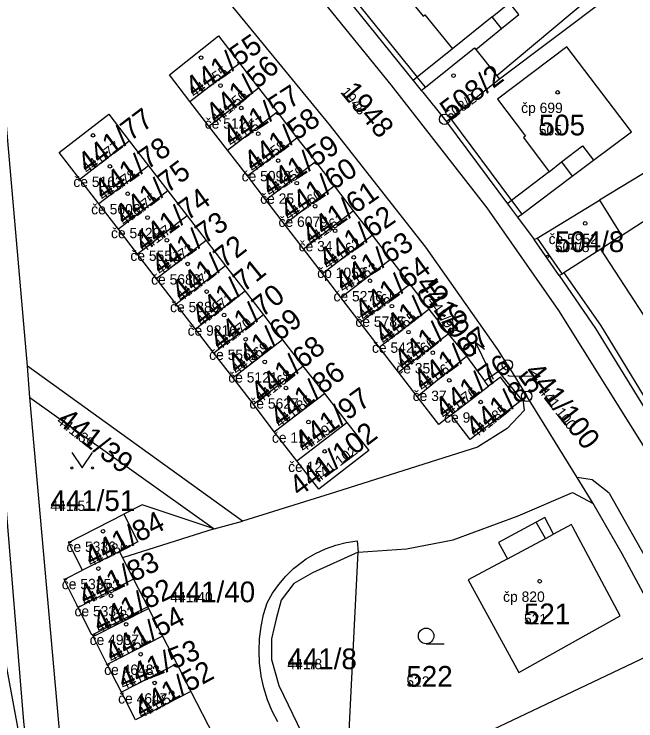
# Model space of a CAD drawing. Extents: x -763628 to -761565, y -976033 to -973833.
# Drawn here: x -762097.5 to -762037.5, y -974221.8 to -974153.6 of the extents above; entities that cross this region are included whole.
import ezdxf

# ---------------------------------------------------------------- set-up
doc = ezdxf.new("R2010")
doc.units = 0
for name, color, linetype in [('KN_cisla parcel 1000', 7, 'Continuous'), ('KN_cisla parcel 500', 7, 'Continuous'), ('KN_cisla parcel znacky', 7, 'Continuous'), ('KN_cisla popisna 500', 7, 'Continuous'), ('KN_hranice parcel', 7, 'Continuous'), ('KN_vnitrni kresba parcel', 7, 'Continuous'), ('KN_znacky bodu BP', 7, 'Continuous'), ('KN_znacky budov', 7, 'Continuous'), ('KN_znacky kultur', 7, 'Continuous')]:
    doc.layers.add(name, color=color, linetype=linetype)

msp = doc.modelspace()

# ---------------------------------------------------------------- linework, layer by layer
at = {"layer": 'KN_cisla parcel znacky'}
for p, q in [((-762052.966, -974185.263), (-762052.977, -974186.382)), ((-762051.65, -974187.96), (-762052.966, -974185.263)), ((-762052.966, -974185.263), (-762052.076, -974185.943)), ((-762051.21, -974188.86), (-762051.65, -974187.96)), ((-762049.72, -974188.5), (-762049.82, -974188.5)), ((-762049.72, -974188.5), (-762046.719, -974188.552)), ((-762046.719, -974188.552), (-762047.73, -974189.036)), ((-762046.719, -974188.552), (-762047.712, -974188.034))]:
    msp.add_line(p, q, dxfattribs=at)
at = {"layer": 'KN_hranice parcel'}
for p, q in [((-762009.82, -974125.16), (-762050.89, -974159.55)), ((-762007.44, -974127.35), (-762050.63, -974159.87)), ((-762065.64, -974151.72), (-762058.96, -974160)), ((-762013.14, -974154.55), (-762040.98, -974171.55)), ((-762052.93, -974157.02), (-762050.89, -974159.55)), ((-762080.5, -974162.03), (-762075.7, -974158.34)), ((-762075.7, -974158.34), (-762073.87, -974160.72)), ((-762058.96, -974160), (-762058.18, -974160.97)), ((-762050.89, -974159.55), (-762050.63, -974159.87)), ((-762078.66, -974164.41), (-762073.87, -974160.72)), ((-762073.87, -974160.72), (-762072.08, -974163.05)), ((-762078.66, -974164.41), (-762080.5, -974162.03)), ((-762076.87, -974166.74), (-762072.08, -974163.05)), ((-762072.08, -974163.05), (-762070.17, -974165.53)), ((-762055.74, -974163.99), (-762049.87, -974171.9)), ((-762076.87, -974166.74), (-762078.66, -974164.41)), ((-762091.12, -974169.52), (-762086.35, -974165.84)), ((-762086.35, -974165.84), (-762084.5, -974168.24)), ((-762074.96, -974169.22), (-762070.17, -974165.53)), ((-762070.17, -974165.53), (-762068.39, -974167.84)), ((-762074.96, -974169.22), (-762076.87, -974166.74)), ((-762073.19, -974171.53), (-762068.39, -974167.84)), ((-762068.39, -974167.84), (-762066.59, -974170.18)), ((-762084.5, -974168.24), (-762089.27, -974171.92)), ((-762084.5, -974168.24), (-762082.63, -974170.67)), ((-762089.27, -974171.92), (-762091.12, -974169.52)), ((-762073.19, -974171.53), (-762074.96, -974169.22)), ((-762071.38, -974173.87), (-762066.59, -974170.18)), ((-762066.59, -974170.18), (-762064.74, -974172.58)), ((-762082.63, -974170.67), (-762087.4, -974174.35)), ((-762082.63, -974170.67), (-762080.77, -974173.08)), ((-762071.38, -974173.87), (-762073.19, -974171.53)), ((-762040.98, -974171.55), (-762038.86, -974174.98)), ((-762087.4, -974174.35), (-762089.27, -974171.92)), ((-762049.87, -974171.9), (-762048.9, -974173.21)), ((-762069.53, -974176.27), (-762064.74, -974172.58)), ((-762064.74, -974172.58), (-762062.93, -974174.94)), ((-762080.77, -974173.08), (-762085.55, -974176.76)), ((-762080.77, -974173.08), (-762078.93, -974175.46)), ((-762048.9, -974173.21), (-762047.31, -974175.35)), ((-762085.55, -974176.76), (-762087.4, -974174.35)), ((-762069.53, -974176.27), (-762071.38, -974173.87)), ((-762067.72, -974178.63), (-762062.93, -974174.94)), ((-762062.93, -974174.94), (-762061.14, -974177.26)), ((-762038.86, -974174.98), (-762040.88, -974176.3)), ((-762078.93, -974175.46), (-762083.71, -974179.14)), ((-762078.93, -974175.46), (-762077.05, -974177.91)), ((-762044.9, -974178.83), (-762047.31, -974175.35)), ((-762067.72, -974178.63), (-762069.53, -974176.27)), ((-762083.71, -974179.14), (-762085.55, -974176.76)), ((-762065.93, -974180.95), (-762061.14, -974177.26)), ((-762061.14, -974177.26), (-762059.28, -974179.68)), ((-762077.05, -974177.91), (-762081.82, -974181.59)), ((-762077.05, -974177.91), (-762075.18, -974180.33)), ((-762065.93, -974180.95), (-762067.72, -974178.63)), ((-762081.82, -974181.59), (-762083.71, -974179.14)), ((-762064.07, -974183.37), (-762059.28, -974179.68)), ((-762059.28, -974179.68), (-762057.44, -974182.07)), ((-762075.18, -974180.33), (-762079.96, -974184.01)), ((-762075.18, -974180.33), (-762073.41, -974182.63)), ((-762064.07, -974183.37), (-762065.93, -974180.95)), ((-762079.96, -974184.01), (-762081.82, -974181.59)), ((-762062.23, -974185.76), (-762057.44, -974182.07)), ((-762057.44, -974182.07), (-762055.59, -974184.46)), ((-762073.41, -974182.63), (-762078.19, -974186.31)), ((-762073.41, -974182.63), (-762071.56, -974185.03)), ((-762062.23, -974185.76), (-762064.07, -974183.37)), ((-762078.19, -974186.31), (-762079.96, -974184.01)), ((-762060.39, -974188.15), (-762055.59, -974184.46)), ((-762055.59, -974184.46), (-762053.81, -974186.61)), ((-762071.56, -974185.03), (-762076.33, -974188.71)), ((-762071.56, -974185.03), (-762069.6, -974187.57)), ((-762060.39, -974188.15), (-762062.23, -974185.76)), ((-762076.33, -974188.71), (-762078.19, -974186.31)), ((-762058.57, -974190.52), (-762053.81, -974186.61)), ((-762053.81, -974186.61), (-762052.08, -974189)), ((-762095.95, -974190.59), (-762096.15, -974187.58)), ((-762075.42, -974202.52), (-762096.15, -974187.58)), ((-762074.37, -974191.25), (-762069.6, -974187.57)), ((-762069.6, -974187.57), (-762067.53, -974190.21)), ((-762050.72, -974188.05), (-762049.88, -974187.46)), ((-762058.57, -974190.52), (-762060.39, -974188.15)), ((-762052.08, -974189), (-762050.72, -974188.05)), ((-762048.48, -974190.83), (-762050.72, -974188.05)), ((-762074.37, -974191.25), (-762076.33, -974188.71)), ((-762051.7, -974189.52), (-762052.08, -974189)), ((-762055.3, -974192.29), (-762051.7, -974189.52)), ((-762092.91, -974224.57), (-762095.95, -974190.59)), ((-762095.95, -974190.59), (-762078.17, -974203.27)), ((-762072.36, -974193.92), (-762067.53, -974190.21)), ((-762067.53, -974190.21), (-762065.35, -974193.02)), ((-762048.01, -974190.48), (-762048.38, -974190.75)), ((-762072.36, -974193.92), (-762074.37, -974191.25)), ((-762048.48, -974190.83), (-762048.71, -974191.01)), ((-762048.38, -974190.75), (-762048.48, -974190.83)), ((-762070.19, -974196.72), (-762065.35, -974193.02)), ((-762070.19, -974196.72), (-762072.36, -974193.92)), ((-762078.17, -974203.27), (-762075.42, -974202.52)), ((-762064.38, -974204.42), (-762064.27, -974205.53)), ((-762087.3, -974205.45), (-762090.86, -974207.26)), ((-762065.49, -974229.39), (-762064.27, -974205.53)), ((-762085.93, -974208.12), (-762091.28, -974210.85)), ((-762085.93, -974208.12), (-762084.57, -974210.79)), ((-762084.57, -974210.79), (-762084.49, -974210.95)), ((-762084.49, -974210.95), (-762083.13, -974213.62)), ((-762083.13, -974213.62), (-762088.47, -974216.35)), ((-762083.13, -974213.62), (-762081.76, -974216.29)), ((-762087.11, -974219.02), (-762088.47, -974216.35)), ((-762081.76, -974216.29), (-762087.11, -974219.02)), ((-762081.76, -974216.29), (-762080.4, -974218.97)), ((-762080.4, -974218.97), (-762078.2, -974223.27))]:
    msp.add_line(p, q, dxfattribs=at)
for points in [[(-762095.33, -974232.49), (-762096.53, -974221.88), (-762099.3, -974188.16), (-762099.59, -974185.1), (-762102.09, -974155.55), (-762101.7, -974155.58), (-762101.97, -974152.44), (-762102.63, -974146.99), (-762101.97, -974146.87), (-762103.48, -974129.95), (-762106.04, -974105.14), (-762113.51, -974051.11), (-762116.06, -974049.38)], [(-762095.33, -974232.49), (-762097.17, -974222.06), (-762100.03, -974206.75), (-762102.48, -974185.96), (-762102.8, -974182.73), (-762109.69, -974112.17), (-762112.36, -974090.26), (-762116.1, -974069.05), (-762118.4, -974057.49)], [(-762096.15, -974187.58), (-762099, -974155.5), (-762099.6, -974155.46), (-762099.73, -974152.5), (-762097.25, -974152.2), (-762097.79, -974146.39), (-762099.76, -974146.71), (-762101.36, -974130.74), (-762099.97, -974129.78), (-762093.64, -974131.74)], [(-762049.88, -974187.46), (-762050.81, -974185.98), (-762057.75, -974176.1), (-762067.06, -974164.24), (-762088, -974138.7)], [(-762052.93, -974157.02), (-762050.43, -974155), (-762048.77, -974153.66), (-762049.69, -974152.52), (-762048.75, -974151.76), (-762054.26, -974144.85), (-762060.82, -974150.05), (-762060.72, -974150.18), (-762060.87, -974150.3), (-762058, -974153.81), (-762057.85, -974153.69), (-762055.18, -974156.95), (-762058.57, -974159.68), (-762058.96, -974160)], [(-762080.5, -974162.03), (-762082.46, -974159.47), (-762077.73, -974155.71), (-762075.7, -974158.34)], [(-762058.18, -974160.97), (-762057.79, -974160.66), (-762053.06, -974156.85), (-762052.93, -974157.02)], [(-762048.9, -974173.21), (-762048.5, -974172.91), (-762043.62, -974169.24), (-762041.58, -974167.71), (-762037.92, -974164.96), (-762044.15, -974156.75), (-762050.83, -974161.82), (-762048.13, -974165.37), (-762048.33, -974165.52), (-762045.86, -974168.84), (-762049.47, -974171.6), (-762049.87, -974171.9)], [(-762050.63, -974159.87), (-762055.36, -974163.68), (-762055.74, -974163.99)], [(-762058.18, -974160.97), (-762058.03, -974161.14), (-762055.93, -974163.76), (-762055.74, -974163.99)], [(-762091.12, -974169.52), (-762093.1, -974166.96), (-762088.33, -974163.27), (-762086.35, -974165.84)], [(-762038.86, -974174.98), (-762035.43, -974172.74), (-762035.05, -974173.33), (-762029.61, -974169.78), (-762024.89, -974176.89), (-762029.9, -974180.17), (-762027.95, -974183.11), (-762033.96, -974186.9), (-762040.88, -974176.3)], [(-762047.31, -974175.35), (-762047.01, -974175.22), (-762046.85, -974175.13), (-762040.98, -974171.55)], [(-762040.88, -974176.3), (-762044.43, -974178.58), (-762044.61, -974178.69), (-762044.9, -974178.83)], [(-762044.9, -974178.83), (-762041.37, -974183.93), (-762036.34, -974192.15)], [(-762049.88, -974187.46), (-762048.48, -974189.71), (-762048.01, -974190.48)], [(-762048.71, -974191.01), (-762050.55, -974188.63), (-762051.7, -974189.52)], [(-762055.3, -974192.29), (-762056.5, -974193.21), (-762058.57, -974190.52)], [(-762041.61, -974200.83), (-762043.16, -974198.32), (-762048.01, -974190.48)], [(-762048.38, -974190.75), (-762048.27, -974191.86), (-762049.89, -974193.6), (-762052.75, -974195.4), (-762066.45, -974199.74), (-762075.42, -974202.52)], [(-762048.71, -974191.01), (-762053.47, -974194.67), (-762055.3, -974192.29)], [(-762065.35, -974193.02), (-762063.25, -974195.73), (-762068.07, -974199.46), (-762070.19, -974196.72)], [(-762064.27, -974205.53), (-762059.62, -974205.2), (-762055.12, -974204.33), (-762048.84, -974202.02), (-762043.61, -974199.77), (-762041.61, -974200.83)], [(-762034.09, -974214.47), (-762038.82, -974205.69), (-762041.61, -974200.83)], [(-762078.17, -974203.27), (-762085.1, -974200.96), (-762086.88, -974201.87)], [(-762090.86, -974207.26), (-762092.22, -974204.59), (-762086.88, -974201.87)], [(-762086.88, -974201.87), (-762085.52, -974204.54), (-762087.3, -974205.45)], [(-762053.66, -974208.21), (-762048.76, -974217.13), (-762039, -974211.66), (-762043.57, -974203.12), (-762043.71, -974202.86), (-762045.42, -974203.78), (-762046.28, -974202.17), (-762047.09, -974202.62), (-762050.73, -974204.59), (-762049.87, -974206.17), (-762053.66, -974208.21)], [(-762072.02, -974221.91), (-762072.558, -974220.856), (-762073.005, -974219.761), (-762073.358, -974218.631), (-762073.615, -974217.476), (-762073.626, -974217.412), (-762073.779, -974216.238), (-762073.832, -974215.056), (-762073.785, -974213.874), (-762073.638, -974212.7), (-762073.392, -974211.543), (-762073.05, -974210.41), (-762072.532, -974209.496), (-762071.929, -974208.636), (-762071.248, -974207.837), (-762070.493, -974207.107), (-762070.126, -974206.798), (-762069.278, -974206.178), (-762068.374, -974205.643), (-762067.424, -974205.195), (-762066.436, -974204.84), (-762065.418, -974204.581), (-762064.38, -974204.42)], [(-762087.3, -974205.45), (-762086.99, -974206.06), (-762085.93, -974208.12)], [(-762064.27, -974205.53), (-762068.69, -974207.52), (-762070.47, -974208.56), (-762071.7, -974210.16), (-762072.19, -974211.96), (-762072.64, -974213.9), (-762072.64, -974215.87), (-762071.92, -974218.39), (-762066.57, -974229.46)], [(-762091.28, -974210.85), (-762092.64, -974208.17), (-762090.86, -974207.26)], [(-762084.57, -974210.79), (-762089.97, -974213.55), (-762091.28, -974210.85)], [(-762088.47, -974216.35), (-762089.84, -974213.68), (-762084.49, -974210.95)], [(-762065.49, -974229.39), (-762034.5, -974214.66), (-762034.09, -974214.47)], [(-762080.4, -974218.97), (-762085.74, -974221.7), (-762087.11, -974219.02)]]:
    msp.add_lwpolyline(points, dxfattribs=at)
at = {"layer": 'KN_vnitrni kresba parcel'}
for p, q in [((-762080.56, -974136.43), (-762061.12, -974160.42)), ((-762065.25, -974151.4), (-762058.57, -974159.68)), ((-762051.35, -974153.86), (-762049.69, -974152.52)), ((-762051.35, -974153.86), (-762055.18, -974156.95)), ((-762050.43, -974155), (-762051.35, -974153.86)), ((-762057.79, -974160.66), (-762058.57, -974159.68)), ((-762061.12, -974160.42), (-762051.86, -974172.31)), ((-762055.36, -974163.68), (-762049.47, -974171.6)), ((-762044.67, -974167.85), (-762042.63, -974166.32)), ((-762042.63, -974166.32), (-762041.58, -974167.71)), ((-762045.86, -974168.84), (-762044.67, -974167.85)), ((-762044.67, -974167.85), (-762043.62, -974169.24)), ((-762049.47, -974171.6), (-762048.5, -974172.91)), ((-762051.86, -974172.31), (-762044.94, -974182.2)), ((-762047.01, -974175.22), (-762044.61, -974178.69)), ((-762044.43, -974178.58), (-762040.9, -974183.62)), ((-762044.94, -974182.2), (-762035.7, -974197.02)), ((-762040.9, -974183.62), (-762035.87, -974191.86)), ((-762041.7, -974198.56), (-762043.16, -974198.32)), ((-762040.07, -974199.84), (-762041.7, -974198.56)), ((-762040.07, -974199.84), (-762032.28, -974213.63)), ((-762046.21, -974204.2), (-762047.09, -974202.62)), ((-762078.17, -974203.27), (-762086.99, -974206.06)), ((-762049.87, -974206.17), (-762046.21, -974204.2)), ((-762046.21, -974204.2), (-762045.42, -974203.78))]:
    msp.add_line(p, q, dxfattribs=at)
at = {"layer": 'KN_znacky bodu BP'}
for centre, radius in [((-762055.93, -974163.76), 0.5), ((-762055.93, -974163.76), 0.0303), ((-762049.88, -974187.46), 0.5), ((-762049.88, -974187.46), 0.0303), ((-762048.01, -974190.48), 0.5), ((-762048.01, -974190.48), 0.0303)]:
    msp.add_circle(centre, radius, dxfattribs=at)
at = {"layer": 'KN_znacky budov'}
for centre, radius in [((-762079.417, -974157.809), 0.175), ((-762055.077, -974159.539), 0.175), ((-762077.547, -974160.499), 0.175), ((-762045.027, -974161.159), 0.175), ((-762075.547, -974162.669), 0.175), ((-762089.847, -974165.309), 0.175), ((-762073.907, -974165.149), 0.175), ((-762088.217, -974168.299), 0.175), ((-762071.987, -974167.749), 0.175), ((-762070.197, -974169.919), 0.175), ((-762086.497, -974170.939), 0.175), ((-762068.427, -974172.149), 0.175), ((-762084.587, -974173.239), 0.175), ((-762042.377, -974173.809), 0.175), ((-762066.487, -974174.509), 0.175), ((-762082.717, -974175.429), 0.175), ((-762064.697, -974177.079), 0.175), ((-762045.992, -974176.986), 0.117), ((-762080.717, -974177.719), 0.175), ((-762063.127, -974179.339), 0.175), ((-762078.887, -974180.379), 0.175), ((-762061.017, -974181.789), 0.175), ((-762077.197, -974182.649), 0.175), ((-762059.417, -974184.299), 0.175), ((-762075.117, -974184.979), 0.175), ((-762057.067, -974186.289), 0.175), ((-762073.277, -974187.169), 0.175), ((-762055.487, -974188.949), 0.175), ((-762071.237, -974189.689), 0.175), ((-762052.457, -974191.039), 0.175), ((-762069.067, -974192.979), 0.175), ((-762067.497, -974195.799), 0.175), ((-762088.877, -974203.509), 0.175), ((-762089.327, -974207.109), 0.175), ((-762046.767, -974208.329), 0.175), ((-762088.107, -974209.729), 0.175), ((-762086.647, -974212.489), 0.175), ((-762085.247, -974215.379), 0.175), ((-762083.897, -974218.149), 0.175)]:
    msp.add_circle(centre, radius, dxfattribs=at)
at = {"layer": 'KN_znacky kultur'}
msp.add_line((-762057.713, -974214.36), (-762055.963, -974214.36), dxfattribs=at)
msp.add_lwpolyline([(-762091.89, -974195.899), (-762090.89, -974197.4), (-762089.89, -974195.899)], dxfattribs=at)
for centre, radius in [((-762091.89, -974197.399), 0.1), ((-762089.89, -974197.399), 0.1), ((-762057.713, -974213.61), 0.75)]:
    msp.add_circle(centre, radius, dxfattribs=at)

# ---------------------------------------------------------------- texts
at = {"layer": 'KN_cisla parcel 1000'}
for s, rotation, p in [('441/55', 35, (-762080.075, -974161.711)), ('441/56', 41, (-762077.916, -974164.292)), ('508/2', 37, (-762055.418, -974163.968)), ('441/57', 33, (-762076.513, -974166.443)), ('1948', 310, (-762066.031, -974161.166)), ('441/77', 37, (-762090.388, -974169.059)), ('441/58', 36, (-762074.397, -974168.915)), ('441/59', 33, (-762072.773, -974171.243)), ('441/78', 35, (-762088.875, -974171.651)), ('441/60', 34, (-762070.964, -974173.557)), ('441/75', 37, (-762086.818, -974174.069)), ('441/61', 35, (-762068.815, -974175.921)), ('441/74', 36, (-762084.947, -974176.655)), ('441/62', 35, (-762067.205, -974178.271)), ('441/73', 35, (-762083.345, -974178.841)), ('441/63', 32, (-762065.722, -974180.508)), ('441/72', 38, (-762081.32, -974181.392)), ('441/64', 36, (-762063.717, -974183.245)), ('441/71', 39, (-762079.352, -974183.776)), ('441/65', 38, (-762061.75, -974185.532)), ('441/70', 38, (-762077.63, -974186.122)), ('441/98', 305, (-762058.803, -974179.657)), ('441/66', 39, (-762059.832, -974188.036)), ('441/69', 38, (-762075.96, -974188.442)), ('441/67', 36, (-762058.047, -974190.045)), ('441/68', 39, (-762073.652, -974191.176)), ('441/76', 36, (-762055.977, -974192.705)), ('441/86', 38, (-762071.81, -974193.562)), ('441/100', 308, (-762048.335, -974188.174)), ('441/85', 39, (-762052.922, -974194.576)), ('441/97', 36, (-762069.506, -974195.924)), ('441/39', 322, (-762093.433, -974193.019)), ('441/102', 37, (-762069.956, -974200.236)), ('441/84', 27, (-762090.047, -974206.964)), ('441/83', 26, (-762090.626, -974210.719)), ('441/82', 26, (-762089.256, -974213.339)), ('441/54', 28, (-762088.028, -974216.229)), ('441/53', 22, (-762086.935, -974218.796)), ('441/52', 29, (-762085.159, -974221.594))]:
    msp.add_text(s, height=2, rotation=rotation, dxfattribs=at).set_placement(p)
for s, p in [('505', (-762046.85, -974165.31)), ('504/8', (-762045.3, -974176.57)), ('441/51', (-762093.95, -974201.55)), ('441/40', (-762082.39, -974210.36)), ('521', (-762048.28, -974212.48)), ('441/8', (-762071.09, -974216.82)), ('522', (-762059.62, -974218.51))]:
    msp.add_text(s, height=2, dxfattribs=at).set_placement(p)
at = {"layer": 'KN_cisla parcel 500'}
for s, rotation, p in [('441/55', 35, (-762080.075, -974161.711)), ('441/56', 41, (-762077.916, -974164.292)), ('1948', 310, (-762066.031, -974161.166)), ('508/2', 37, (-762055.418, -974163.968)), ('441/57', 33, (-762076.513, -974166.443)), ('441/77', 37, (-762090.388, -974169.059)), ('441/58', 36, (-762074.397, -974168.915)), ('441/78', 35, (-762088.875, -974171.651)), ('441/59', 33, (-762072.773, -974171.243)), ('441/75', 37, (-762086.818, -974174.069)), ('441/60', 34, (-762070.964, -974173.557)), ('441/61', 35, (-762068.815, -974175.921)), ('441/74', 36, (-762084.947, -974176.655)), ('441/62', 35, (-762067.205, -974178.271)), ('441/73', 35, (-762083.345, -974178.841)), ('441/63', 32, (-762065.722, -974180.508)), ('441/72', 38, (-762081.32, -974181.392)), ('441/64', 36, (-762063.717, -974183.245)), ('441/71', 39, (-762079.352, -974183.776)), ('441/98', 305, (-762057.665, -974181.282)), ('441/65', 38, (-762061.75, -974185.532)), ('441/70', 38, (-762077.63, -974186.122)), ('441/69', 38, (-762075.96, -974188.442)), ('441/66', 39, (-762059.832, -974188.036)), ('441/67', 36, (-762058.047, -974190.045)), ('441/68', 39, (-762073.652, -974191.176)), ('441/76', 36, (-762055.977, -974192.705)), ('441/100', 308, (-762046.908, -974190)), ('441/86', 38, (-762071.81, -974193.562)), ('441/85', 39, (-762052.922, -974194.576)), ('441/39', 322, (-762093.433, -974193.019)), ('441/97', 36, (-762069.506, -974195.924)), ('441/102', 37, (-762068.105, -974198.841)), ('441/84', 27, (-762090.047, -974206.964)), ('441/83', 26, (-762090.626, -974210.719)), ('441/82', 26, (-762089.256, -974213.339)), ('441/54', 28, (-762088.028, -974216.229)), ('441/53', 22, (-762086.935, -974218.796)), ('441/52', 29, (-762085.159, -974221.594))]:
    msp.add_text(s, height=1, rotation=rotation, dxfattribs=at).set_placement(p)
for s, p in [('505', (-762046.85, -974165.31)), ('504/8', (-762045.3, -974176.57)), ('441/51', (-762093.95, -974201.55)), ('441/40', (-762082.39, -974210.36)), ('521', (-762048.28, -974212.48)), ('441/8', (-762071.09, -974216.82)), ('522', (-762059.62, -974218.51))]:
    msp.add_text(s, height=1, dxfattribs=at).set_placement(p)
at = {"layer": 'KN_cisla popisna 500'}
for s, p in [('čp 699', (-762048.551, -974163.151)), ('če 5124', (-762079.071, -974164.661)), ('če 5098', (-762075.511, -974169.741)), ('če 5163', (-762091.741, -974170.291)), ('če 25', (-762073.721, -974171.911)), ('če 5606', (-762090.021, -974172.931)), ('če 6079', (-762071.951, -974174.141)), ('če 5429', (-762088.111, -974175.231)), ('če 5952', (-762045.901, -974175.801)), ('če 34', (-762070.011, -974176.501)), ('če 5551', (-762086.241, -974177.421)), ('čp 1058', (-762068.221, -974179.071)), ('če 5680', (-762084.241, -974179.711)), ('če 5276', (-762066.651, -974181.331)), ('če 5389', (-762082.411, -974182.371)), ('če 5785', (-762064.541, -974183.781)), ('če 9216', (-762080.721, -974184.641)), ('če 5425', (-762062.941, -974186.291)), ('če 5562', (-762078.641, -974186.971)), ('če 35', (-762060.591, -974188.281)), ('če 5121', (-762076.801, -974189.161)), ('če 37', (-762059.011, -974190.941)), ('če 5627', (-762074.761, -974191.681)), ('če 9', (-762055.981, -974193.031)), ('če 11', (-762072.591, -974194.971)), ('če 12', (-762071.021, -974197.791)), ('če 5336', (-762092.401, -974205.501)), ('če 5335', (-762092.851, -974209.101)), ('čp 820', (-762050.291, -974210.321)), ('če 5334', (-762091.631, -974211.721)), ('če 4937', (-762090.171, -974214.481)), ('če 4648', (-762088.771, -974217.371)), ('če 4647', (-762087.421, -974220.141))]:
    msp.add_text(s, height=1, dxfattribs=at).set_placement(p)

doc.saveas('drawing.dxf')
